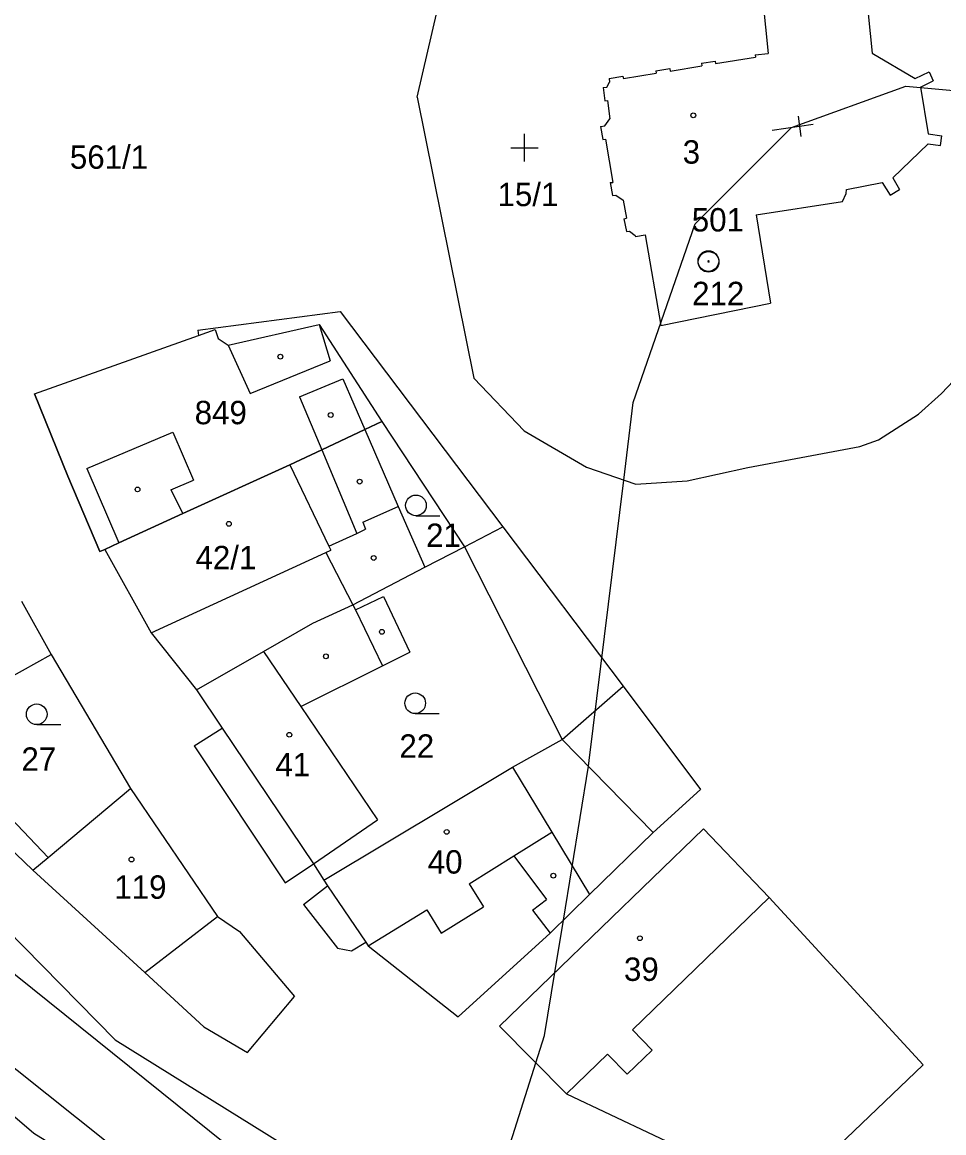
# Model space of a CAD drawing. Extents: x -725765 to -723182, y -1052705 to -1049154.
# Drawn here: x -724756.6 to -724689.6, y -1050950.1 to -1050869.4 of the extents above; entities that cross this region are included whole.
import ezdxf

# ---------------------------------------------------------------- set-up
doc = ezdxf.new("R2010")
doc.units = 0
for name, color, linetype in [('Vrstva 1', 7, 'Continuous'), ('Vrstva 17', 7, 'Continuous'), ('Vrstva 18', 7, 'Continuous'), ('Vrstva 19', 7, 'Continuous'), ('Vrstva 25', 7, 'Continuous'), ('Vrstva 4', 7, 'Continuous'), ('Vrstva 52', 7, 'Continuous')]:
    doc.layers.add(name, color=color, linetype=linetype)

msp = doc.modelspace()

# ---------------------------------------------------------------- linework, layer by layer
at = {"layer": 'Vrstva 1'}
for points in [[(-724695.28, -1050867.04), (-724694.82, -1050871.61)], [(-724702.77, -1050867.8), (-724702.38, -1050871.62)], [(-724727.89, -1050874.8), (-724726.42, -1050868.43)], [(-724703.33, -1050871.72), (-724702.38, -1050871.62)], [(-724703.33, -1050871.72), (-724703.3, -1050871.89)], [(-724694.82, -1050871.61), (-724691.7, -1050873.45)], [(-724709.5, -1050872.9), (-724707.2, -1050872.52)], [(-724707.23, -1050872.33), (-724706.24, -1050872.17)], [(-724707.23, -1050872.33), (-724707.2, -1050872.52)], [(-724706.24, -1050872.17), (-724706.21, -1050872.36)], [(-724706.21, -1050872.36), (-724703.3, -1050871.89)], [(-724713.94, -1050873.45), (-724712.93, -1050873.27)], [(-724713.94, -1050873.45), (-724713.9, -1050873.71)], [(-724712.93, -1050873.27), (-724712.9, -1050873.45)], [(-724712.9, -1050873.45), (-724710.51, -1050873.06)], [(-724710.54, -1050872.89), (-724709.52, -1050872.72)], [(-724710.54, -1050872.89), (-724710.51, -1050873.06)], [(-724709.52, -1050872.72), (-724709.5, -1050872.9)], [(-724691.7, -1050873.45), (-724690.67, -1050872.95)], [(-724690.67, -1050872.95), (-724690.38, -1050873.6)], [(-724714.37, -1050874.09), (-724714.11, -1050874.06)], [(-724714.37, -1050874.09), (-724714.25, -1050875.07)], [(-724714.11, -1050874.06), (-724713.9, -1050873.71)], [(-724691.3, -1050874.07), (-724690.38, -1050873.6)], [(-724691.3, -1050874.07), (-724690.74, -1050877.47)], [(-724727.89, -1050874.8), (-724723.76, -1050895.23)], [(-724714.25, -1050875.07), (-724714.06, -1050875.05)], [(-724714.06, -1050875.05), (-724713.89, -1050876.38)], [(-724714.26, -1050876.87), (-724713.89, -1050876.38)], [(-724714.57, -1050876.92), (-724714.26, -1050876.87)], [(-724714.57, -1050876.92), (-724714.4, -1050877.88)], [(-724690.74, -1050877.47), (-724689.75, -1050877.61)], [(-724714.4, -1050877.88), (-724714.2, -1050877.84)], [(-724714.2, -1050877.84), (-724713.67, -1050880.99)], [(-724693.31, -1050880.65), (-724690.76, -1050878.18)], [(-724690.76, -1050878.18), (-724689.85, -1050878.31)], [(-724689.85, -1050878.31), (-724689.75, -1050877.61)], [(-724693.31, -1050880.65), (-724692.84, -1050881.5)], [(-724713.85, -1050881.01), (-724713.67, -1050880.99)], [(-724713.85, -1050881.01), (-724713.69, -1050881.95)], [(-724696.7, -1050881.8), (-724696.69, -1050881.5)], [(-724696.69, -1050881.5), (-724694.09, -1050881)], [(-724694.09, -1050881), (-724693.51, -1050881.92)], [(-724693.51, -1050881.92), (-724692.84, -1050881.5)], [(-724713.69, -1050881.95), (-724713.45, -1050881.91)], [(-724713.45, -1050881.91), (-724712.92, -1050882.28)], [(-724712.92, -1050882.28), (-724712.68, -1050883.6)], [(-724703.24, -1050883.34), (-724696.97, -1050882.37)], [(-724696.97, -1050882.37), (-724696.7, -1050881.8)], [(-724712.86, -1050883.63), (-724712.68, -1050883.6)], [(-724712.86, -1050883.63), (-724712.68, -1050884.57)], [(-724703.24, -1050883.34), (-724702.22, -1050889.78)], [(-724712.68, -1050884.57), (-724712.45, -1050884.53)], [(-724712.45, -1050884.53), (-724712.04, -1050884.85)], [(-724712.04, -1050884.85), (-724712.01, -1050884.93)], [(-724712.01, -1050884.93), (-724711.31, -1050884.81)], [(-724711.31, -1050884.81), (-724710.19, -1050891.4)], [(-724710.19, -1050891.4), (-724702.22, -1050889.78)], [(-724743.77, -1050892.12), (-724742.57, -1050891.69)], [(-724742.57, -1050891.69), (-724742.34, -1050892.35)], [(-724741.63, -1050892.83), (-724735, -1050891.32)], [(-724735, -1050891.32), (-724730.46, -1050898.38)], [(-724755.69, -1050896.36), (-724743.77, -1050892.12)], [(-724742.34, -1050892.35), (-724741.63, -1050892.83)], [(-724723.76, -1050895.23), (-724720.11, -1050899.04)], [(-724689.77, -1050896.34), (-724688.06, -1050894.53)], [(-724755.69, -1050896.36), (-724753.28, -1050902.35)], [(-724691.45, -1050897.84), (-724689.77, -1050896.34)], [(-724731.69, -1050898.96), (-724730.46, -1050898.38)], [(-724730.46, -1050898.38), (-724724.45, -1050907.47)], [(-724694.35, -1050899.7), (-724691.45, -1050897.84)], [(-724734.82, -1050900.43), (-724731.69, -1050898.96)], [(-724720.11, -1050899.04), (-724715.59, -1050901.69)], [(-724695.71, -1050900.2), (-724694.35, -1050899.7)], [(-724737.15, -1050901.52), (-724734.82, -1050900.43)], [(-724703.86, -1050901.72), (-724695.71, -1050900.2)], [(-724744.91, -1050905.06), (-724737.15, -1050901.52)], [(-724737.15, -1050901.52), (-724734.31, -1050907.44)], [(-724715.59, -1050901.69), (-724712, -1050902.93)], [(-724708.26, -1050902.69), (-724703.86, -1050901.72)], [(-724753.28, -1050902.35), (-724750.94, -1050907.83)], [(-724712, -1050902.93), (-724708.26, -1050902.69)], [(-724749.58, -1050907.19), (-724744.91, -1050905.06)], [(-724750.6, -1050907.67), (-724749.58, -1050907.19)], [(-724750.94, -1050907.83), (-724750.6, -1050907.67)], [(-724750.6, -1050907.67), (-724747.21, -1050913.73)], [(-724734.53, -1050907.9), (-724734.17, -1050907.73)], [(-724734.53, -1050907.9), (-724732.57, -1050911.69)], [(-724734.31, -1050907.44), (-724734.17, -1050907.73)], [(-724727.33, -1050908.97), (-724724.45, -1050907.47)], [(-724724.45, -1050907.47), (-724717.34, -1050921.48)], [(-724732.57, -1050911.69), (-724727.33, -1050908.97)], [(-724756.65, -1050911.44), (-724754.49, -1050915.3)], [(-724735.47, -1050913.02), (-724732.57, -1050911.69)], [(-724739.05, -1050915.09), (-724735.47, -1050913.02)], [(-724747.21, -1050913.73), (-724743.92, -1050917.87)], [(-724769.61, -1050914.39), (-724754.7, -1050930.05)], [(-724760.77, -1050918.8), (-724754.49, -1050915.3)], [(-724754.49, -1050915.3), (-724748.72, -1050925.04)], [(-724743.92, -1050917.87), (-724739.05, -1050915.09)], [(-724739.05, -1050915.09), (-724736.34, -1050919.09)], [(-724743.92, -1050917.87), (-724742.05, -1050920.66)], [(-724736.34, -1050919.09), (-724730.77, -1050927.32)], [(-724742.05, -1050920.66), (-724735.43, -1050930.51)], [(-724720.97, -1050923.49), (-724717.34, -1050921.48)], [(-724717.34, -1050921.48), (-724710.74, -1050928.25)], [(-724734.66, -1050931.72), (-724720.97, -1050923.49)], [(-724754.7, -1050930.05), (-724748.72, -1050925.04)], [(-724748.72, -1050925.04), (-724742.4, -1050934.35)], [(-724767.07, -1050925.79), (-724749.83, -1050943.31)], [(-724735.43, -1050930.51), (-724730.77, -1050927.32)], [(-724721.91, -1050942.31), (-724707.08, -1050927.98)], [(-724715.37, -1050932.75), (-724710.74, -1050928.25)], [(-724707.08, -1050927.98), (-724702.31, -1050932.97)], [(-724755.82, -1050930.98), (-724754.7, -1050930.05)], [(-724735.43, -1050930.51), (-724734.66, -1050931.72)], [(-724755.82, -1050930.98), (-724747.69, -1050938.43)], [(-724734.66, -1050931.72), (-724734.4, -1050932.11)], [(-724734.4, -1050932.11), (-724731.62, -1050936.22)], [(-724718.23, -1050935.57), (-724715.37, -1050932.75)], [(-724702.31, -1050932.97), (-724691.11, -1050945.12)], [(-724742.4, -1050934.35), (-724740.8, -1050935.44)], [(-724740.8, -1050935.44), (-724736.8, -1050940.16)], [(-724724.91, -1050941.63), (-724718.23, -1050935.57)], [(-724731.62, -1050936.22), (-724731.45, -1050936.47)], [(-724731.45, -1050936.47), (-724724.91, -1050941.63)], [(-724769.97, -1050937.91), (-724755.76, -1050950.09)], [(-724747.69, -1050938.43), (-724743.39, -1050942.38)], [(-724740.21, -1050944.23), (-724736.8, -1050940.16)], [(-724743.39, -1050942.38), (-724740.21, -1050944.23)], [(-724721.91, -1050942.31), (-724717.03, -1050947.24)], [(-724749.83, -1050943.31), (-724735.73, -1050952.08)], [(-724701.16, -1050954.75), (-724691.11, -1050945.12)], [(-724717.03, -1050947.24), (-724701.16, -1050954.75)]]:
    msp.add_lwpolyline(points, dxfattribs=at)
at = {"layer": 'Vrstva 25'}
for points in [[(-724700.21, -1050876.17), (-724699.993, -1050877.653)], [(-724720.09, -1050879.47), (-724720.09, -1050877.47)], [(-724702.08, -1050877.2), (-724699.112, -1050876.767)], [(-724721.09, -1050878.47), (-724719.09, -1050878.47)], [(-724727.98, -1050905.22), (-724726.23, -1050905.22)], [(-724728.03, -1050919.6), (-724726.28, -1050919.6)], [(-724755.54, -1050920.4), (-724753.79, -1050920.4)]]:
    msp.add_lwpolyline(points, dxfattribs=at)
for centre, radius in [((-724707.82, -1050876.12), 0.175), ((-724706.72, -1050886.71), 0.75), ((-724706.71, -1050886.77), 0.75), ((-724706.72, -1050886.71), 0.032), ((-724706.71, -1050886.77), 0.032), ((-724737.83, -1050893.66), 0.175), ((-724734.17, -1050897.9), 0.175), ((-724748.21, -1050903.31), 0.175), ((-724732.07, -1050902.74), 0.175), ((-724727.98, -1050904.47), 0.75), ((-724741.57, -1050905.81), 0.175), ((-724731.05, -1050908.29), 0.175), ((-724730.45, -1050913.66), 0.175), ((-724734.52, -1050915.44), 0.175), ((-724728.03, -1050918.85), 0.75), ((-724755.54, -1050919.65), 0.75), ((-724737.18, -1050921.14), 0.175), ((-724725.74, -1050928.2), 0.175), ((-724748.65, -1050930.21), 0.175), ((-724717.99, -1050931.38), 0.175), ((-724711.7, -1050935.93), 0.175)]:
    msp.add_circle(centre, radius, dxfattribs=at)
at = {"layer": 'Vrstva 4'}
for points in [[(-724743.82, -1050891.73), (-724733.48, -1050890.38)], [(-724733.48, -1050890.38), (-724721.66, -1050906.03)], [(-724743.82, -1050891.73), (-724743.77, -1050892.12)], [(-724735, -1050891.32), (-724734.21, -1050893.96)], [(-724741.63, -1050892.83), (-724740.02, -1050896.34)], [(-724740.02, -1050896.34), (-724734.21, -1050893.96)], [(-724736.43, -1050896.58), (-724733.28, -1050895.28)], [(-724733.28, -1050895.28), (-724731.69, -1050898.96)], [(-724736.43, -1050896.58), (-724734.82, -1050900.43)], [(-724751.9, -1050901.78), (-724745.65, -1050899.15)], [(-724745.65, -1050899.15), (-724744.15, -1050902.63)], [(-724731.69, -1050898.96), (-724729.26, -1050904.56)], [(-724734.82, -1050900.43), (-724732.27, -1050906.51)], [(-724751.9, -1050901.78), (-724749.58, -1050907.19)], [(-724745.78, -1050903.33), (-724744.15, -1050902.63)], [(-724745.78, -1050903.33), (-724744.91, -1050905.06)], [(-724731.84, -1050905.7), (-724729.26, -1050904.56)], [(-724729.26, -1050904.56), (-724727.33, -1050908.97)], [(-724731.84, -1050905.7), (-724731.64, -1050906.19)], [(-724734.31, -1050907.44), (-724732.27, -1050906.51)], [(-724732.27, -1050906.51), (-724731.64, -1050906.19)], [(-724724.45, -1050907.47), (-724721.66, -1050906.03)], [(-724721.66, -1050906.03), (-724712.92, -1050917.61)], [(-724747.21, -1050913.73), (-724734.53, -1050907.9)], [(-724732.38, -1050912.06), (-724730.33, -1050911.09)], [(-724730.33, -1050911.09), (-724728.41, -1050915.13)], [(-724732.57, -1050911.69), (-724732.38, -1050912.06)], [(-724732.38, -1050912.06), (-724730.42, -1050916.14)], [(-724730.42, -1050916.14), (-724728.41, -1050915.13)], [(-724736.34, -1050919.09), (-724730.42, -1050916.14)], [(-724717.34, -1050921.48), (-724712.92, -1050917.61)], [(-724712.92, -1050917.61), (-724707.29, -1050925.13)], [(-724744.1, -1050921.94), (-724742.05, -1050920.66)], [(-724744.1, -1050921.94), (-724737.48, -1050931.91)], [(-724720.97, -1050923.49), (-724718.11, -1050928.22)], [(-724762.62, -1050924.46), (-724755.82, -1050930.98)], [(-724710.74, -1050928.25), (-724707.29, -1050925.13)], [(-724720.86, -1050929.94), (-724718.11, -1050928.22)], [(-724718.11, -1050928.22), (-724715.37, -1050932.75)], [(-724724.11, -1050931.97), (-724720.86, -1050929.94)], [(-724720.86, -1050929.94), (-724718.49, -1050933.12)], [(-724737.48, -1050931.91), (-724735.43, -1050930.51)], [(-724736.16, -1050933.47), (-724734.4, -1050932.11)], [(-724724.11, -1050931.97), (-724723.07, -1050933.65)], [(-724764.15, -1050932.92), (-724737.04, -1050954.71)], [(-724719.5, -1050933.88), (-724718.49, -1050933.12)], [(-724712.24, -1050942.59), (-724702.31, -1050932.97)], [(-724736.16, -1050933.47), (-724733.67, -1050936.66)], [(-724731.45, -1050936.47), (-724727.18, -1050933.87)], [(-724727.18, -1050933.87), (-724726.14, -1050935.55)], [(-724726.14, -1050935.55), (-724723.07, -1050933.65)], [(-724719.5, -1050933.88), (-724718.23, -1050935.57)], [(-724747.69, -1050938.43), (-724742.4, -1050934.35)], [(-724732.65, -1050936.85), (-724731.62, -1050936.22)], [(-724767.77, -1050936.91), (-724739.7, -1050959.28)], [(-724733.67, -1050936.66), (-724732.65, -1050936.85)], [(-724712.24, -1050942.59), (-724710.81, -1050944.06)], [(-724717.03, -1050947.24), (-724714.05, -1050944.35)], [(-724714.05, -1050944.35), (-724712.62, -1050945.82)], [(-724712.62, -1050945.82), (-724710.81, -1050944.06)]]:
    msp.add_lwpolyline(points, dxfattribs=at)
at = {"layer": 'Vrstva 52'}
for points in [[(-724813.33, -1050644), (-724808.37, -1050650.73), (-724806.43, -1050654.63), (-724804.75, -1050661.51), (-724810.21, -1050691.79), (-724815, -1050731.09), (-724815.58, -1050758.85), (-724815.13, -1050787.45), (-724817.4, -1050803.09), (-724819.59, -1050825.69), (-724818.46, -1050833.53), (-724815.27, -1050842.75), (-724807.1, -1050869.67), (-724799.84, -1050887.62), (-724790.58, -1050905.75), (-724781.27, -1050921.4), (-724774.72, -1050931.91), (-724769.97, -1050937.91), (-724755.76, -1050950.09), (-724747.39, -1050955.27), (-724740.23, -1050960.06), (-724733.48, -1050964.31), (-724729, -1050967.94)], [(-724797.81, -1050648.79), (-724786.08, -1050660.92), (-724787.52, -1050665.42), (-724789.04, -1050670.2), (-724789.99, -1050673.16), (-724795.12, -1050673.64), (-724798.75, -1050677.64), (-724800.93, -1050691.71), (-724804.92, -1050728), (-724806.68, -1050763.03), (-724806.76, -1050807.12), (-724807.68, -1050827.87), (-724807.91, -1050834.06), (-724802.7, -1050857.13), (-724793.87, -1050880.36), (-724784.64, -1050902.78), (-724767.07, -1050925.79), (-724749.83, -1050943.31), (-724735.73, -1050952.08), (-724724.93, -1050961.09)], [(-724724.93, -1050961.09), (-724723.69, -1050959), (-724719.26, -1050944.99), (-724718.63, -1050943), (-724717.88, -1050938.42), (-724717.26, -1050934.62), (-724715.44, -1050923.42), (-724715.38, -1050923), (-724712.88, -1050902.63), (-724712.19, -1050897), (-724707.69, -1050884), (-724700.69, -1050877), (-724692.38, -1050874), (-724685.73, -1050874.61), (-724681.5, -1050875), (-724671.31, -1050882), (-724668.84, -1050884.53), (-724650.81, -1050903), (-724630.31, -1050928), (-724612.38, -1050961), (-724597.47, -1050993.67)], [(-724735, -1050891.32), (-724730.46, -1050898.38), (-724731.69, -1050898.96), (-724734.82, -1050900.43), (-724737.15, -1050901.52), (-724744.91, -1050905.06), (-724749.58, -1050907.19), (-724750.6, -1050907.67), (-724750.94, -1050907.83), (-724753.28, -1050902.35), (-724755.69, -1050896.36), (-724743.77, -1050892.12), (-724742.57, -1050891.69), (-724742.34, -1050892.35), (-724741.63, -1050892.83), (-724735, -1050891.32)]]:
    msp.add_lwpolyline(points, dxfattribs=at)

# ---------------------------------------------------------------- texts
at = {"layer": 'Vrstva 17'}
for s, p in [('501', (-724707.93, -1050884.56)), ('212', (-724707.905, -1050889.917))]:
    msp.add_text(s, height=1.7, dxfattribs=at).set_placement(p)
at = {"layer": 'Vrstva 18'}
for s, p in [('561/1', (-724753.13, -1050880)), ('15/1', (-724722.05, -1050882.72)), ('849', (-724744.06, -1050898.57)), ('21', (-724727.24, -1050907.49)), ('22', (-724729.18, -1050922.81)), ('27', (-724756.65, -1050923.76))]:
    msp.add_text(s, height=1.7, dxfattribs=at).set_placement(p)
at = {"layer": 'Vrstva 19'}
for s, p in [('3', (-724708.59, -1050879.63)), ('42/1', (-724744, -1050909.11)), ('41', (-724738.19, -1050924.16)), ('40', (-724727.12, -1050931.23)), ('119', (-724749.9, -1050933.06)), ('39', (-724712.86, -1050939.03))]:
    msp.add_text(s, height=1.7, dxfattribs=at).set_placement(p)

doc.saveas('drawing.dxf')
